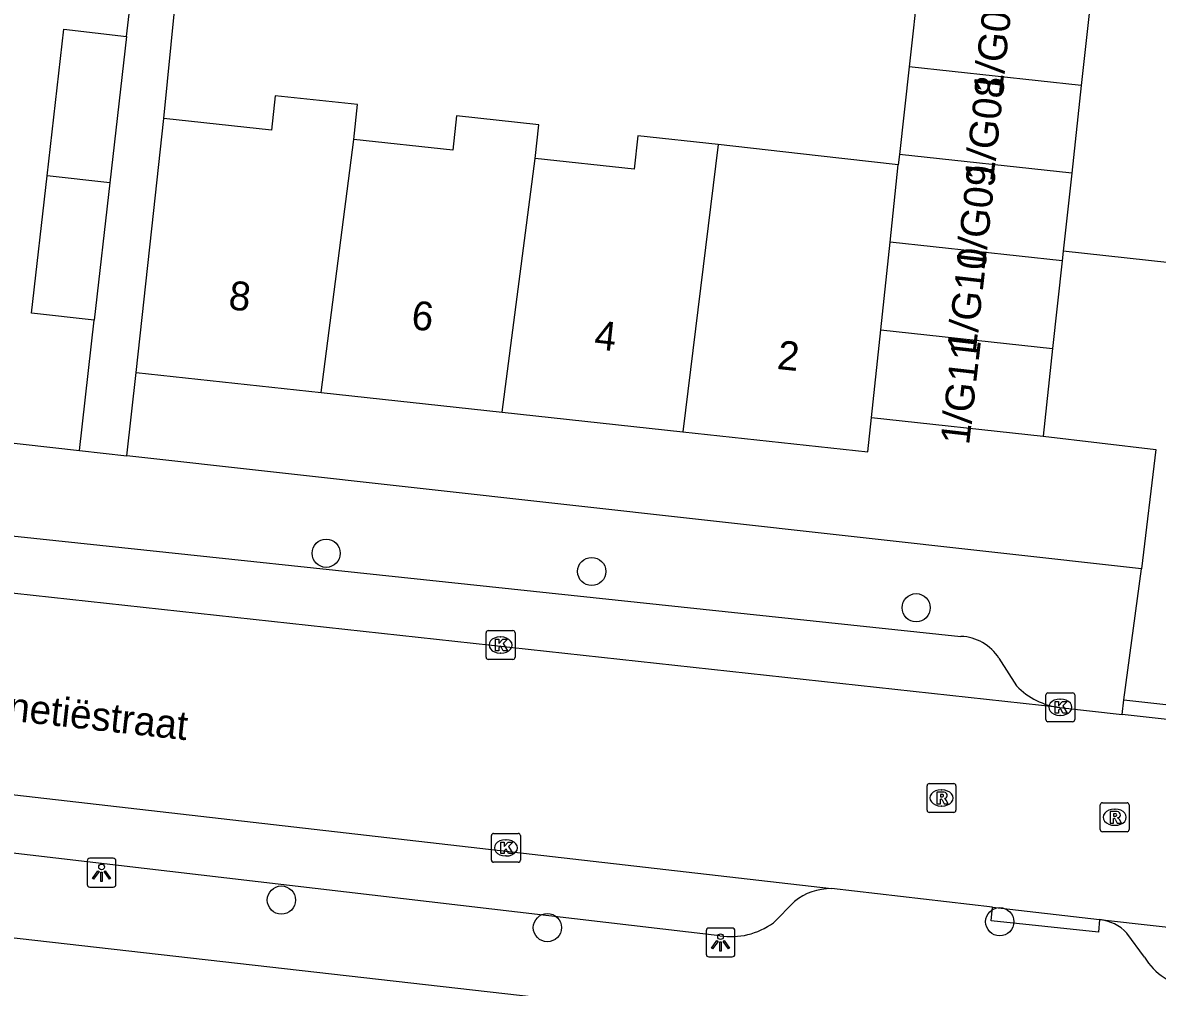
# Model space of a CAD drawing. Extents: x 162082 to 163393, y 388091 to 388632.
# Drawn here: x 162764.83 to 162804.15, y 388336.96 to 388370.39 of the extents above; entities that cross this region are included whole.
import ezdxf

# ---------------------------------------------------------------- set-up
doc = ezdxf.new("R2010")
doc.units = 0
for name, color, linetype in [('IMGEO_Boom', 7, 'Continuous'), ('IMGEO_Kolk', 7, 'Continuous'), ('IMGEO_Lichtpunt', 7, 'Continuous'), ('IMGEO_Openbare_ruimte_label', 7, 'Continuous'), ('IMGEO_Pand', 7, 'Continuous'), ('IMGEO_Pand_nummerreeks', 7, 'Continuous'), ('IMGEO_Rijbaan_lokaal_open', 7, 'Continuous'), ('IMGEO_Rioolput', 7, 'Continuous'), ('IMGEO_Voetpad_open', 7, 'Continuous')]:
    doc.layers.add(name, color=color, linetype=linetype)

msp = doc.modelspace()

# ---------------------------------------------------------------- linework, layer by layer
at = {"layer": 'IMGEO_Boom'}
for centre in [(162775.343, 388352.006), (162784.544, 388351.373), (162795.789, 388350.118), (162773.791, 388339.985), (162783.009, 388339.03), (162798.685, 388339.235)]:
    msp.add_circle(centre, 0.489, dxfattribs=at)
at = {"layer": 'IMGEO_Kolk'}
for p, q in [((162780.886, 388348.399), (162780.886, 388349.251)), ((162780.961, 388349.325), (162781.813, 388349.325)), ((162781.374, 388349.105), (162781.399, 388349.105)), ((162781.887, 388349.251), (162781.887, 388348.399)), ((162781.813, 388348.325), (162780.961, 388348.325)), ((162781.397, 388348.545), (162781.372, 388348.545)), ((162800.282, 388346.241), (162800.282, 388347.093)), ((162800.357, 388347.167), (162801.209, 388347.167)), ((162801.283, 388347.093), (162801.283, 388346.241)), ((162800.77, 388346.947), (162800.795, 388346.947)), ((162800.793, 388346.387), (162800.768, 388346.387)), ((162801.209, 388346.167), (162800.357, 388346.167)), ((162781.146, 388342.295), (162781.998, 388342.295)), ((162781.071, 388341.369), (162781.071, 388342.221)), ((162781.559, 388342.075), (162781.584, 388342.075)), ((162782.072, 388342.221), (162782.072, 388341.369)), ((162781.582, 388341.515), (162781.557, 388341.515)), ((162781.998, 388341.295), (162781.146, 388341.295))]:
    msp.add_line(p, q, dxfattribs=at)
for points in [[(162780.886, 388348.399), (162780.886, 388349.251)], [(162780.961, 388349.325), (162781.813, 388349.325)], [(162781.207, 388349.025), (162781.33, 388349.025), (162781.33, 388348.874), (162781.46, 388349.025), (162781.624, 388349.025), (162781.478, 388348.874), (162781.631, 388348.625), (162781.479, 388348.625), (162781.394, 388348.789), (162781.33, 388348.722), (162781.33, 388348.625), (162781.207, 388348.625), (162781.207, 388349.025)], [(162781.887, 388349.251), (162781.887, 388348.399)], [(162781.813, 388348.325), (162780.961, 388348.325)], [(162800.282, 388346.241), (162800.282, 388347.093)], [(162800.357, 388347.167), (162801.209, 388347.167)], [(162801.283, 388347.093), (162801.283, 388346.241)], [(162800.603, 388346.867), (162800.726, 388346.867), (162800.726, 388346.716), (162800.856, 388346.867), (162801.02, 388346.867), (162800.874, 388346.716), (162801.027, 388346.467), (162800.875, 388346.467), (162800.79, 388346.631), (162800.726, 388346.564), (162800.726, 388346.467), (162800.603, 388346.467), (162800.603, 388346.867)], [(162801.209, 388346.167), (162800.357, 388346.167)], [(162781.146, 388342.295), (162781.998, 388342.295)], [(162781.071, 388341.369), (162781.071, 388342.221)], [(162781.392, 388341.995), (162781.515, 388341.995), (162781.515, 388341.844), (162781.645, 388341.995), (162781.809, 388341.995), (162781.663, 388341.844), (162781.816, 388341.595), (162781.664, 388341.595), (162781.579, 388341.759), (162781.515, 388341.692), (162781.515, 388341.595), (162781.392, 388341.595), (162781.392, 388341.995)], [(162782.072, 388342.221), (162782.072, 388341.369)], [(162781.998, 388341.295), (162781.146, 388341.295)]]:
    msp.add_lwpolyline(points, dxfattribs=at)
for centre, start, end in [((162780.963, 388349.249), 91.552, 178.448), ((162780.963, 388349.249), 91.552, 178.448), ((162781.811, 388349.249), 1.552, 88.448), ((162781.811, 388349.249), 1.552, 88.448), ((162780.963, 388348.401), 181.552, 268.448), ((162780.963, 388348.401), 181.552, 268.448), ((162781.811, 388348.401), 271.552, 358.448), ((162781.811, 388348.401), 271.552, 358.448), ((162800.359, 388347.091), 91.552, 178.448), ((162800.359, 388347.091), 91.552, 178.448), ((162801.207, 388347.091), 1.552, 88.448), ((162801.207, 388347.091), 1.552, 88.448), ((162800.359, 388346.243), 181.552, 268.448), ((162800.359, 388346.243), 181.552, 268.448), ((162801.207, 388346.243), 271.552, 358.448), ((162801.207, 388346.243), 271.552, 358.448), ((162781.148, 388342.219), 91.552, 178.448), ((162781.148, 388342.219), 91.552, 178.448), ((162781.996, 388342.219), 1.552, 88.448), ((162781.996, 388342.219), 1.552, 88.448), ((162781.148, 388341.371), 181.552, 268.448), ((162781.148, 388341.371), 181.552, 268.448), ((162781.996, 388341.371), 271.552, 358.448), ((162781.996, 388341.371), 271.552, 358.448)]:
    msp.add_arc(centre, 0.0765, start, end, dxfattribs=at)
for centre, major_axis, ratio, start_param, end_param in [((162781.373, 388348.825), (-0.387, 0.002), 0.722429, 4.712389, 7.853982), ((162781.398, 388348.825), (-0.39, 0.002), 0.717154, 1.570796, 4.712389), ((162800.769, 388346.667), (-0.387, 0.002), 0.722429, 4.712389, 7.853982), ((162800.794, 388346.667), (-0.39, 0.002), 0.717154, 1.570796, 4.712389), ((162781.558, 388341.795), (-0.387, 0.002), 0.722429, 4.712389, 7.853982), ((162781.583, 388341.795), (-0.39, 0.002), 0.717154, 1.570796, 4.712389)]:
    msp.add_ellipse(centre, major_axis=major_axis, ratio=ratio, start_param=start_param, end_param=end_param, dxfattribs=at)
at = {"layer": 'IMGEO_Lichtpunt'}
for p, q in [((162767.061, 388341.338), (162767.061, 388340.531)), ((162767.061, 388341.338), (162767.061, 388340.531)), ((162767.963, 388341.433), (162767.155, 388341.433)), ((162767.963, 388341.433), (162767.155, 388341.433)), ((162768.057, 388340.531), (162768.057, 388341.338)), ((162768.057, 388340.531), (162768.057, 388341.338)), ((162767.155, 388340.437), (162767.963, 388340.437)), ((162767.155, 388340.437), (162767.963, 388340.437)), ((162788.511, 388338.92), (162788.511, 388338.113)), ((162788.511, 388338.92), (162788.511, 388338.113)), ((162789.413, 388339.015), (162788.605, 388339.015)), ((162789.413, 388339.015), (162788.605, 388339.015)), ((162789.507, 388338.113), (162789.507, 388338.92)), ((162789.507, 388338.113), (162789.507, 388338.92)), ((162788.605, 388338.019), (162789.413, 388338.019)), ((162788.605, 388338.019), (162789.413, 388338.019))]:
    msp.add_line(p, q, dxfattribs=at)
for points in [[(162767.435, 388341.002), (162767.474, 388340.974), (162767.286, 388340.712), (162767.248, 388340.739), (162767.435, 388341.002)], [(162767.537, 388340.954), (162767.584, 388340.954), (162767.584, 388340.632), (162767.537, 388340.632), (162767.537, 388340.954)], [(162767.647, 388340.974), (162767.685, 388341.001), (162767.872, 388340.739), (162767.833, 388340.711), (162767.647, 388340.974)], [(162788.885, 388338.584), (162788.924, 388338.556), (162788.736, 388338.294), (162788.698, 388338.321), (162788.885, 388338.584)], [(162788.987, 388338.536), (162789.034, 388338.536), (162789.034, 388338.214), (162788.987, 388338.214), (162788.987, 388338.536)], [(162789.097, 388338.556), (162789.135, 388338.583), (162789.322, 388338.321), (162789.283, 388338.293), (162789.097, 388338.556)]]:
    msp.add_lwpolyline(points, dxfattribs=at)
for centre in [(162767.56, 388341.136), (162789.01, 388338.718)]:
    msp.add_circle(centre, 0.0994, dxfattribs=at)
for centre, start, end in [((162767.155, 388341.338), 90, 180), ((162767.155, 388341.338), 90, 180), ((162767.963, 388341.338), 0, 90), ((162767.963, 388341.338), 0, 90), ((162767.155, 388340.531), 180, 270), ((162767.155, 388340.531), 180, 270), ((162767.963, 388340.531), 270, 0), ((162767.963, 388340.531), 270, 360), ((162788.605, 388338.92), 90, 180), ((162788.605, 388338.92), 90, 180), ((162789.413, 388338.92), 0, 90), ((162789.413, 388338.92), 0, 90), ((162788.605, 388338.113), 180, 270), ((162788.605, 388338.113), 180, 270), ((162789.413, 388338.113), 270, 0), ((162789.413, 388338.113), 270, 360)]:
    msp.add_arc(centre, 0.0946, start, end, dxfattribs=at)
at = {"layer": 'IMGEO_Pand'}
for points in [[(162795.883, 388371.895), (162795.545, 388368.859)], [(162801.839, 388371.247), (162801.509, 388368.211)], [(162765.67, 388365.081), (162766.25, 388370.165), (162768.428, 388369.917)], [(162768.428, 388369.917), (162767.849, 388364.843)], [(162795.545, 388368.859), (162795.206, 388365.824)], [(162801.509, 388368.211), (162795.545, 388368.859)], [(162801.509, 388368.211), (162801.179, 388365.175)], [(162776.3, 388366.345), (162776.431, 388367.551), (162773.579, 388367.861), (162773.449, 388366.664), (162769.716, 388367.07)], [(162768.76, 388358.274), (162769.3, 388363.245), (162769.716, 388367.07)], [(162782.589, 388365.683), (162782.716, 388366.85), (162779.861, 388367.16), (162779.732, 388365.972), (162776.3, 388366.345)], [(162775.173, 388357.576), (162776.3, 388366.345)], [(162788.932, 388366.17), (162786.143, 388366.473), (162786.017, 388365.31), (162782.589, 388365.683)], [(162788.932, 388366.17), (162787.701, 388356.214)], [(162795.167, 388365.47), (162792.389, 388365.772), (162788.932, 388366.17)], [(162781.437, 388356.895), (162782.589, 388365.683)], [(162794.884, 388362.787), (162795.167, 388365.47)], [(162795.206, 388365.824), (162795.167, 388365.47)], [(162801.179, 388365.175), (162795.206, 388365.824)], [(162767.306, 388360.079), (162765.128, 388360.327), (162765.67, 388365.081)], [(162767.849, 388364.843), (162765.67, 388365.081)], [(162801.179, 388365.175), (162800.885, 388362.477)], [(162767.849, 388364.843), (162767.306, 388360.079)], [(162794.564, 388359.75), (162794.884, 388362.787)], [(162800.848, 388362.138), (162794.884, 388362.787)], [(162800.885, 388362.477), (162800.848, 388362.138)], [(162800.848, 388362.138), (162800.518, 388359.102)], [(162794.244, 388356.712), (162794.564, 388359.75)], [(162794.564, 388359.75), (162800.518, 388359.102)], [(162800.518, 388359.102), (162800.188, 388356.066)], [(162768.76, 388358.274), (162775.173, 388357.576)], [(162775.173, 388357.576), (162781.437, 388356.895)], [(162781.437, 388356.895), (162787.701, 388356.214)], [(162787.701, 388356.214), (162794.114, 388355.516), (162794.244, 388356.712)], [(162794.244, 388356.712), (162800.188, 388356.066)]]:
    msp.add_lwpolyline(points, dxfattribs=at)
at = {"layer": 'IMGEO_Rijbaan_lokaal_open'}
for points in [[(162809.756, 388361.499), (162800.885, 388362.477)], [(162800.77, 388346.657), (162746.114, 388352.626)], [(162800.77, 388346.657), (162802.929, 388346.416)], [(162808.22, 388345.824), (162802.929, 388346.416)], [(162745.211, 388345.846), (162792.851, 388340.382)], [(162798.436, 388339.741), (162792.851, 388340.382)], [(162798.436, 388339.741), (162802.146, 388339.314)], [(162802.146, 388339.314), (162880.401, 388330.569)]]:
    msp.add_lwpolyline(points, dxfattribs=at)
at = {"layer": 'IMGEO_Rioolput'}
for p, q in [((162796.166, 388343.098), (162796.166, 388343.95)), ((162796.241, 388344.024), (162797.093, 388344.024)), ((162797.167, 388343.95), (162797.167, 388343.098)), ((162796.654, 388343.804), (162796.679, 388343.804)), ((162796.677, 388343.244), (162796.652, 388343.244)), ((162802.169, 388342.43), (162802.169, 388343.282)), ((162802.244, 388343.356), (162803.096, 388343.356)), ((162802.657, 388343.136), (162802.682, 388343.136)), ((162803.17, 388343.282), (162803.17, 388342.43)), ((162797.093, 388343.024), (162796.241, 388343.024)), ((162803.096, 388342.356), (162802.244, 388342.356)), ((162802.68, 388342.576), (162802.655, 388342.576))]:
    msp.add_line(p, q, dxfattribs=at)
for points in [[(162796.166, 388343.098), (162796.166, 388343.95)], [(162796.241, 388344.024), (162797.093, 388344.024)], [(162797.167, 388343.95), (162797.167, 388343.098)], [(162796.755, 388343.722), (162796.503, 388343.724), (162796.503, 388343.324)], [(162796.503, 388343.324), (162796.627, 388343.324), (162796.627, 388343.486), (162796.638, 388343.486)], [(162796.681, 388343.643), (162796.627, 388343.643), (162796.627, 388343.562)], [(162796.627, 388343.562), (162796.679, 388343.562)], [(162796.685, 388343.457), (162796.756, 388343.324), (162796.896, 388343.324), (162796.831, 388343.45)], [(162802.169, 388342.43), (162802.169, 388343.282)], [(162802.244, 388343.356), (162803.096, 388343.356)], [(162802.758, 388343.054), (162802.506, 388343.056), (162802.506, 388342.656)], [(162803.17, 388343.282), (162803.17, 388342.43)], [(162797.093, 388343.024), (162796.241, 388343.024)], [(162802.506, 388342.656), (162802.63, 388342.656), (162802.63, 388342.818), (162802.641, 388342.818)], [(162802.684, 388342.975), (162802.63, 388342.975), (162802.63, 388342.894)], [(162802.63, 388342.894), (162802.682, 388342.894)], [(162802.688, 388342.789), (162802.759, 388342.656), (162802.899, 388342.656), (162802.834, 388342.782)], [(162803.096, 388342.356), (162802.244, 388342.356)]]:
    msp.add_lwpolyline(points, dxfattribs=at)
for centre, radius, start, end in [((162796.243, 388343.948), 0.0765, 91.552, 178.448), ((162796.243, 388343.948), 0.0765, 91.552, 178.448), ((162797.091, 388343.948), 0.0765, 1.552, 88.448), ((162797.091, 388343.948), 0.0765, 1.552, 88.448), ((162796.637, 388343.433), 0.0533, 26.0293, 88.6989), ((162796.663, 388343.751), 0.19, 274.7715, 282.9687), ((162796.687, 388343.547), 0.0964, 77.0061, 93.1865), ((162796.701, 388343.604), 0.0378, 276.6634, 79.6772), ((162796.754, 388343.612), 0.109, 350.3612, 89.416), ((162796.752, 388343.612), 0.112, 277.5842, 350.9817), ((162796.736, 388343.397), 0.108, 29.5134, 73.7905), ((162796.243, 388343.1), 0.0765, 181.552, 268.448), ((162796.243, 388343.1), 0.0765, 181.552, 268.448), ((162797.091, 388343.1), 0.0765, 271.552, 358.448), ((162797.091, 388343.1), 0.0765, 271.552, 358.448), ((162802.246, 388343.28), 0.0765, 91.552, 178.448), ((162802.246, 388343.28), 0.0765, 91.552, 178.448), ((162802.757, 388342.944), 0.109, 350.3612, 89.416), ((162803.094, 388343.28), 0.0765, 1.552, 88.448), ((162803.094, 388343.28), 0.0765, 1.552, 88.448), ((162802.64, 388342.765), 0.0533, 26.0293, 88.6989), ((162802.666, 388343.083), 0.19, 274.7715, 282.9687), ((162802.69, 388342.879), 0.0964, 77.0061, 93.1865), ((162802.704, 388342.936), 0.0378, 276.6634, 79.6772), ((162802.755, 388342.944), 0.112, 277.5842, 350.9817), ((162802.739, 388342.729), 0.108, 29.5134, 73.7905), ((162802.246, 388342.432), 0.0765, 181.552, 268.448), ((162802.246, 388342.432), 0.0765, 181.552, 268.448), ((162803.094, 388342.432), 0.0765, 271.552, 358.448), ((162803.094, 388342.432), 0.0765, 271.552, 358.448)]:
    msp.add_arc(centre, radius, start, end, dxfattribs=at)
for centre, major_axis, ratio, start_param, end_param in [((162796.653, 388343.524), (-0.387, 0.002), 0.722429, 4.712389, 7.853982), ((162796.678, 388343.524), (-0.39, 0.002), 0.717154, 1.570796, 4.712389), ((162802.656, 388342.856), (-0.387, 0.002), 0.722429, 4.712389, 7.853982), ((162802.681, 388342.856), (-0.39, 0.002), 0.717154, 1.570796, 4.712389)]:
    msp.add_ellipse(centre, major_axis=major_axis, ratio=ratio, start_param=start_param, end_param=end_param, dxfattribs=at)
at = {"layer": 'IMGEO_Voetpad_open'}
for points in [[(162768.428, 388369.917), (162770.21, 388385.113), (162772.078, 388401.51)], [(162769.716, 388367.07), (162770.742, 388377.46), (162770.916, 388377.441)], [(162766.793, 388355.568), (162767.306, 388360.079)], [(162768.432, 388355.385), (162768.76, 388358.274)], [(162757.132, 388356.646), (162766.793, 388355.568)], [(162800.188, 388356.066), (162804.094, 388355.604), (162803.599, 388351.461)], [(162766.793, 388355.568), (162768.432, 388355.385)], [(162803.599, 388351.461), (162768.432, 388355.385)], [(162749.629, 388354.18), (162797.34, 388349.123)], [(162802.982, 388346.924), (162803.599, 388351.461)], [(162798.659, 388348.367), (162799.271, 388347.407)], [(162802.929, 388346.416), (162802.982, 388346.924)], [(162802.982, 388346.924), (162808.274, 388346.335), (162808.22, 388345.824)], [(162788.983, 388338.749), (162747.992, 388343.538)], [(162793.443, 388335.388), (162740.3, 388341.413)], [(162791.572, 388339.942), (162790.84, 388339.201)], [(162802.146, 388339.314), (162802.11, 388338.872), (162798.383, 388339.267), (162798.436, 388339.741)], [(162803.705, 388338.011), (162803.094, 388338.843)]]:
    msp.add_lwpolyline(points, dxfattribs=at)
for centre, radius, start, end in [((162797.285, 388347.499), 1.625, 32.2862, 88.0745), ((162801.078, 388349.145), 2.507, 223.8907, 262.9486), ((162792.816, 388338.406), 1.976, 88.9736, 128.9948), ((162789.367, 388341.211), 2.492, 261.1303, 306.2296), ((162801.926, 388337.682), 1.647, 44.835, 82.3254), ((162805.545, 388339.084), 2.13, 210.2575, 263.6897)]:
    msp.add_arc(centre, radius, start, end, dxfattribs=at)

# ---------------------------------------------------------------- texts
at = {"layer": 'IMGEO_Openbare_ruimte_label'}
msp.add_text('Venetiëstraat', height=1, rotation=353.6851, dxfattribs=at).set_placement((162762.659, 388346.393))
at = {"layer": 'IMGEO_Pand_nummerreeks'}
for s, rotation, p in [('1/G07', 83.4685, (162798.756, 388367.872)), ('1/G08', 83.4685, (162798.454, 388364.854)), ('1/G09', 83.4685, (162798.152, 388361.777)), ('1/G10', 83.4685, (162797.847, 388358.906)), ('8', 353.7918, (162771.932, 388360.464)), ('6', 353.7918, (162778.266, 388359.775)), ('4', 353.7918, (162784.605, 388359.085)), ('2', 353.7918, (162790.941, 388358.396)), ('1/G11', 83.4685, (162797.621, 388355.737))]:
    msp.add_text(s, height=1, rotation=rotation, dxfattribs=at).set_placement(p)

doc.saveas('drawing.dxf')
